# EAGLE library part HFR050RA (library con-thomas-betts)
THOMAS&BETTS
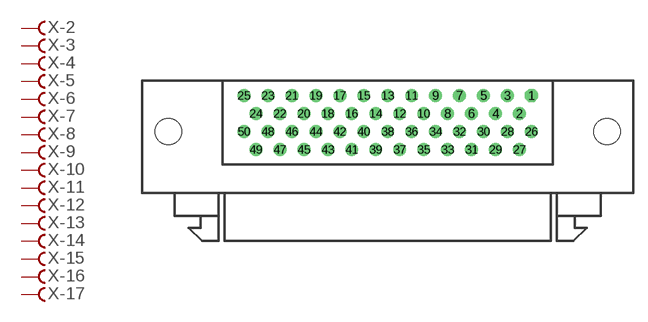
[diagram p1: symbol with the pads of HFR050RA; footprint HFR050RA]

Designator prefix X; gates -2=F -3=F -4=F -5=F -6=F -7=F -8=F -9=F -10=F -11=F -12=F -13=F -14=F -15=F -16=F -17=F -18=F -19=F -20=F -21=F -22=F -23=F -24=F -25=F -27=F -28=F -29=F -30=F -31=F -32=F -33=F -34=F -35=F -36=F -37=F -38=F -39=F -40=F -41=F -42=F -43=F -44=F -45=F -46=F -47=F -48=F -49=F -50=F -1=FV -26=F

## HFR050RA (OC_FARNELL: unknown; OC_NEWARK: unknown)  [HFR050RA]
1  -1:F  pas
2  -2:F  pas
3  -3:F  pas
4  -4:F  pas
5  -5:F  pas
6  -6:F  pas
7  -7:F  pas
8  -8:F  pas
9  -9:F  pas
10  -10:F  pas
11  -11:F  pas
12  -12:F  pas
13  -13:F  pas
14  -14:F  pas
15  -15:F  pas
16  -16:F  pas
17  -17:F  pas
18  -18:F  pas
19  -19:F  pas
20  -20:F  pas
21  -21:F  pas
22  -22:F  pas
23  -23:F  pas
24  -24:F  pas
25  -25:F  pas
26  -26:F  pas
27  -27:F  pas
28  -28:F  pas
29  -29:F  pas
30  -30:F  pas
31  -31:F  pas
32  -32:F  pas
33  -33:F  pas
34  -34:F  pas
35  -35:F  pas
36  -36:F  pas
37  -37:F  pas
38  -38:F  pas
39  -39:F  pas
40  -40:F  pas
41  -41:F  pas
42  -42:F  pas
43  -43:F  pas
44  -44:F  pas
45  -45:F  pas
46  -46:F  pas
47  -47:F  pas
48  -48:F  pas
49  -49:F  pas
50  -50:F  pas

## Footprint HFR050RA (pad centres in mm)
THOMAS&BETTS Fine Pitch "D" Connector HFR050RA29xxx
drill 0.864 octagon: 1 15.24,8.89
drill 0.864 round: 2 13.97,6.98; 3 12.7,8.89; 4 11.43,6.98; 5 10.16,8.89; 6 8.89,6.98; 7 7.62,8.89; 8 6.35,6.98; 9 5.08,8.89; 10 3.81,6.98; 11 2.54,8.89; 12 1.27,6.98; 13 0,8.89; 14 -1.27,6.98; 15 -2.54,8.89; 16 -3.81,6.98; 17 -5.08,8.89; 18 -6.35,6.98; 19 -7.62,8.89; 20 -8.89,6.98; 21 -10.16,8.89; 22 -11.43,6.98; 23 -12.7,8.89; 24 -13.97,6.98; 25 -15.24,8.89; 26 15.24,5.07; 27 13.97,3.16; 28 12.7,5.07; 29 11.43,3.16; 30 10.16,5.07; 31 8.89,3.16; 32 7.62,5.07; 33 6.35,3.16; 34 5.08,5.07; 35 3.81,3.16; 36 2.54,5.07; 37 1.27,3.16; 38 0,5.07; 39 -1.27,3.16; 40 -2.54,5.07; 41 -3.81,3.16; 42 -5.08,5.07; 43 -6.35,3.16; 44 -7.62,5.07; 45 -8.89,3.16; 46 -10.16,5.07; 47 -11.43,3.16; 48 -12.7,5.07; 49 -13.97,3.16; 50 -15.24,5.07
hole 2.769 at 23.241,5.07
hole 2.769 at -23.241,5.07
